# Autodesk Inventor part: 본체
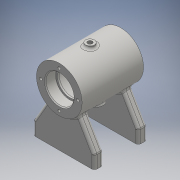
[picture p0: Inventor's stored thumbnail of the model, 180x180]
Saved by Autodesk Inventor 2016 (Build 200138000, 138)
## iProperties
Created: 2018-05
Part Number: 본체
Material: 일반
Document SubType Name: Modeling
Designer: USER
Density: 1 g/cm^3
Appearance: 기본값
Author: USER
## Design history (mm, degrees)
sketch "스케치1"
  geometry: C1 r 26 at (0, 0); 1 further point
  constraints: 1 centre point, 1 coincident
  dimensions: "d0" = 52 diameter of C1
extrude "돌출1" new body sketch "스케치1" stored distance "d1" = 70; taper "d2" = 0 deg
node "작업 평면1"
sketch "스케치2"
  geometry: L1 (0, 0)-(0, -65); L2 (0, -65)-(35, -65); L3 (35, -65)-(35, -50); L4 (35, -50)-(17.325, -19.386); L5 (0, -65)-(-35, -65); L6 (-35, -65)-(-35, -50); L7 (-35, -50)-(-17.325, -19.386); A1 r 26 centre (0, 0) between (-17.325, -19.386) and (17.325, -19.386)
  constraints: 14 end point, 3 symmetric about line, 2 point on circle, 2 vertical, 1 centre point, 1 coincident, 1 horizontal
  dimensions: "d4" = 65 distance of L1.start L1.end; "d5" = 35 distance of L1.end L2.end; "d6" = 15 distance of L2.end L3.end; "d7" = 30 deg angle of L3 L4; "d8" = 52 diameter of A1
extrude "돌출2" join sketch "스케치2" distance "d9" = 10; taper "d10" = 0 deg
sketch "스케치3"
  geometry: L1 (70, -10)-(0, -10) reference; 2 further points
  dimensions: "d11" = 20 horizontal distance of point (15, -5) point (35, 20); "d12" = 5 distance from line of L1 point (15, -5)
hole "구멍1" sketch "스케치3" at (15, -5) diameter "d13" = 4.134; stored, may be unused: countersink angle "d17" = 90 deg, drill point angle "d19" = 118 deg; dims "d14" = 8, "d15" = 4, "d16" = 2, "d18" = 10
sketch "스케치4"
  geometry: L1 (0, 0)-(46.636, 0); L2 (0, 0)-(-48.62, 0); L3 (35, -26)-(35, 26) reference; L4 (35, 16)-(23, 16); L5 (23, 16)-(23, 14); L6 (23, 14)-(21, 14); L7 (21, 14)-(21, 21); L8 (21, 21)-(-21, 21); L9 (-23, 16)-(-35, 16); L10 (-35, 26)-(-35, -26) reference; L11 (-35, 16)-(-35, 0); L12 (35, 16)-(35, 0); L13 (-35, 0)-(35, 0); L14 (-21, 21)-(-21, 14); L15 (-21, 14)-(-23, 14); L16 (-23, 14)-(-23, 16)
  constraints: 28 end point, 6 perpendicular, 4 horizontal, 2 midpoint, 2 point on line, 1 vertical
  dimensions: "d20" = 32 diameter of L4 L1; "d21" = 28 diameter of L6 L1; "d22" = 42 diameter of L8 L1; "d23" = 12 distance between parallel lines of L12 L5; "d25" = 28 diameter of L15 L2; "d26" = 32 diameter of L9 L2; "d27" = 12 distance between parallel lines of L11 L16; "d28" = 42 distance of L7.end L8.end; "d29" = 2 distance of L14.end L15.end
revolve "회전1" sketch "스케치4" stored, may be unused: angle "d30" = 90 deg
node "작업 평면4"
  node "작업 평면3"
sketch "스케치5"
  geometry: C1 r 5 at (0, 0); 1 further point
  constraints: 1 centre point, 1 coincident
  dimensions: "d32" = 10 diameter of C1
extrude "돌출3" join sketch "스케치5" stored distance "d33" = 10; taper "d34" = 0 deg
sketch "스케치6"
  geometry: 2 further points
  constraints: 1 coincident
hole "구멍2" sketch "스케치6" at (0, 0) diameter "d35" = 5.188; stored, may be unused: countersink angle "d39" = 90 deg, drill point angle "d41" = 118 deg; dims "d36" = 12, "d37" = 4, "d38" = 2, "d40" = 16
sketch "스케치7" dims "d42" = 42
  geometry: 3 further points
  constraints: 2 vertical alignment, 1 coincident, 2 other
hole "구멍3" sketch "스케치7" at (0, 21) diameter "d43" = 3.242; stored, may be unused: countersink angle "d47" = 90 deg, drill point angle "d49" = 118 deg; dims "d44" = 8, "d45" = 4, "d46" = 2, "d48" = 10
fillet "모깎기1" dims "d53" = 0.3
fillet "모깎기2" dims "d54" = 3
fillet "모깎기3" dims "d55" = 3
fillet "모깎기4" dims "d56" = 3
fillet "모깎기5" dims "d57" = 3
chamfer "모따기1" distance "d58" = 1; stored, may be unused: second distance "d59" = 2, angle "d60" = 45 deg
node "작업 평면5"
sketch "스케치9"
  geometry: L1 (0, 0)-(0, -40.059); L2 (0, 0)-(-9.919, -27.251)
  constraints: 4 end point, 1 vertical
  dimensions: "d63" = 29 distance of L1.start L2.end; "d64" = 20 deg angle of L1 L2
node "작업 평면6"
sketch "스케치10"
  geometry: C1 r 6 at (0, 0); 1 further point
  constraints: 1 centre point, 1 coincident
  dimensions: "d65" = 12 diameter of C1
extrude "돌출4" join sketch "스케치10" stored distance "d66" = 10; taper "d67" = 0 deg
sketch "스케치11"
  geometry: 2 further points
  constraints: 1 coincident
hole "구멍4" sketch "스케치11" at (0, 0) diameter "d68" = 5.188; stored, may be unused: countersink angle "d72" = 90 deg, drill point angle "d74" = 118 deg; dims "d69" = 12, "d70" = 4, "d71" = 2, "d73" = 16
fillet "모깎기6" dims "d75" = 2
node "작업 평면7"
node "작업 평면8"
sketch "스케치13"
  geometry: 2 further points
  constraints: 1 coincident, 1 other
feature "엠보싱2" sketch "스케치13" dims "d0" = 52, "d82" = 0.5, "d83" = 0
node "솔리드1"
mirror "대칭1"
mirror "대칭2"
mirror "대칭3"
pattern_circular "원형 패턴1" dims angle "d51" = 360 deg
mirror "대칭4"
node "작업 평면2"
other parameters: "d31" = 3, "d61" = 20 deg, "d76" = 26, "d81" = -26
